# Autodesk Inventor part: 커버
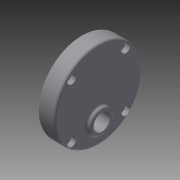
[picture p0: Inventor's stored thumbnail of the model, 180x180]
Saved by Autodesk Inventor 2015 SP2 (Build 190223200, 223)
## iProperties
Created: 2015-06
Part Number: 커버
Material: 일반
Document SubType Name: Modeling
Designer: AMC
Density: 1 g/cm^3
Appearance: 기본값
Author: AMC
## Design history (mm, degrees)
sketch "스케치2"
  geometry: C1 r 40 at (0, 0); 1 further point
  constraints: 1 centre point, 1 coincident
  dimensions: "d5" = 80 diameter of C1
extrude "돌출1" new body sketch "스케치2" distance "d6" = 16; taper "d7" = 0 deg
sketch "스케치3"
  geometry: L1 (0, 0)-(-24.749, 24.749); L2 (0, 0)-(0, 35); A1 r 35 centre (0, 0) between (-24.749, 24.749) and (0, 35); 2 further points
  constraints: 4 end point, 2 coincident, 2 point on circle, 1 centre point, 1 vertical
  dimensions: "d8" = 70 diameter of A1; "d9" = 45 deg angle of L1 L2
hole "구멍1" sketch "스케치3" at (-24.749, 24.749) diameter "d10" = 4; stored, may be unused: countersink angle "d14" = 90 deg, drill point angle "d16" = 118 deg; dims "d11" = 6, "d12" = 8, "d13" = 4.4, "d15" = 8
sketch "스케치11"
  geometry: C1 r 11 at (20, 0); 1 further point
  constraints: 1 centre point, 1 horizontal alignment
  dimensions: "d42" = 22 diameter of C1; "d43" = 20 distance of C1.centre point (0, 0)
extrude "돌출8" join sketch "스케치11" distance "d44" = 3; taper "d45" = 0 deg
sketch "스케치12"
  geometry: C1 r 7.5 at (0, 0); 1 further point
  constraints: 1 centre point, 1 horizontal alignment
  dimensions: "d46" = 15 diameter of C1
extrude "돌출9" cut sketch "스케치12" stored distance "d47" = 10; taper "d48" = 0 deg
sketch "스케치16"
  geometry: C1 r 11 at (-20, 0); 1 further point
  constraints: 1 centre point, 1 horizontal alignment
  dimensions: "d56" = 22 diameter of C1; "d57" = 20 distance of C1.centre point (0, 0)
extrude "돌출12" join sketch "스케치16" distance "d58" = 3; taper "d59" = 0 deg
sketch "스케치17"
  geometry: C1 r 7.5 at (0, 0); 1 further point
  constraints: 1 centre point
  dimensions: "d60" = 15 diameter of C1
extrude "돌출13" cut sketch "스케치17" distance "d61" = 3; taper "d62" = 0 deg
sketch "스케치18"
  geometry: C1 r 11 at (-11, 0); 1 further point
  constraints: 1 centre point, 1 horizontal alignment
  dimensions: "d63" = 11 distance of point (0, 0) C1.centre; "d64" = 22 diameter of C1
extrude "돌출14" join sketch "스케치18" distance "d65" = 3; taper "d66" = 0 deg
sketch "스케치19"
  geometry: C1 r 9 at (0, 0); 1 further point
  constraints: 1 centre point
  dimensions: "d67" = 18 diameter of C1
extrude "돌출15" cut sketch "스케치19" distance "d68" = 8; taper "d69" = 0 deg
fillet "모깎기1" dims "d70" = 0.3
fillet "모깎기2" dims "d71" = 0.3
fillet "모깎기3" dims "d72" = 2
fillet "모깎기4" dims "d73" = 2
fillet "모깎기5" dims "d74" = 2
node "솔리드2"
pattern_circular "원형 패턴1" dims angle "d18" = 360 deg
